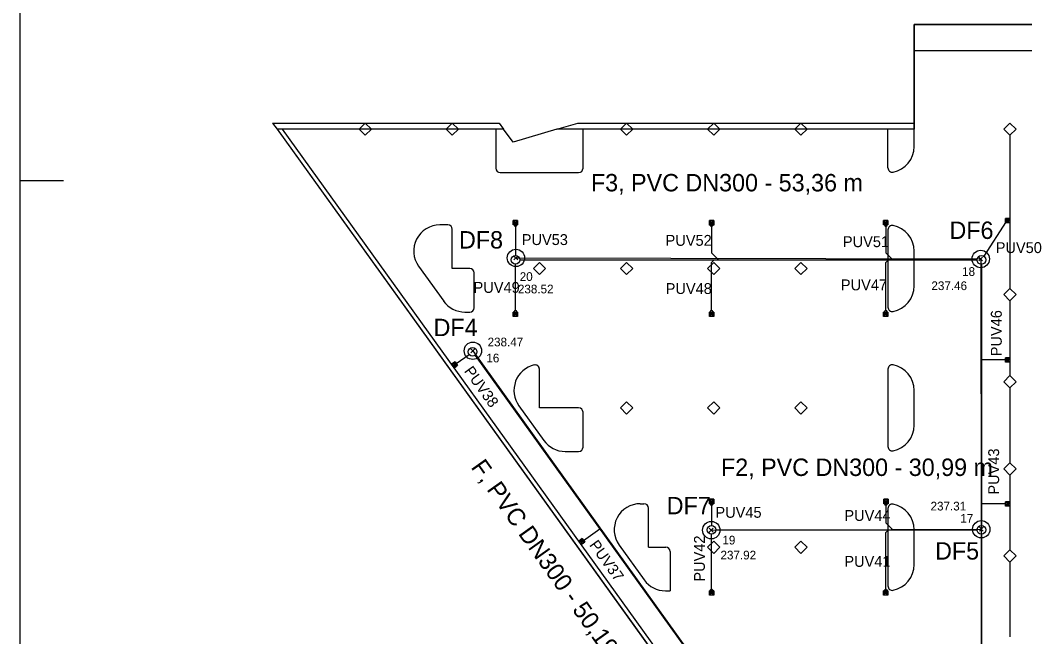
# Model space of a CAD drawing. Extents: x -264234 to -263604, y -1242346 to -1242049.
# Drawn here: x -264234.2 to -264118.9, y -1242249.8 to -1242179 of the extents above; entities that cross this region are included whole.
import ezdxf

# ---------------------------------------------------------------- set-up
doc = ezdxf.new("R2010")
doc.units = 0
for name, color, linetype in [('KFA_BODY_CISLO', 7, 'Continuous'), ('KFA_BODY_SYMBOL', 7, 'Continuous'), ('KFA_BODY_VYSKA', 7, 'Continuous'), ('KFA_DAZDOVA_KANALIZACIA_vetva_F', 7, 'Continuous'), ('KFA_DAZDOVA_KANALIZACIA_vetva_F_popis', 7, 'Continuous'), ('KFA_SITUACIA_DSP', 7, 'Continuous'), ('KFA_SO_40-2-II_DK_PRIPOJKY_UV_PROJEKT', 7, 'Continuous'), ('KFA_SO_40-2-II_DK_PRIPOJKY_UV_PROJEKT_popis', 7, 'Continuous'), ('KFA_SO_40-2-II_DK_UV_PROJEKT', 7, 'Continuous'), ('RAM_NA_TLAC_1-500', 7, 'Continuous')]:
    doc.layers.add(name, color=color, linetype=linetype)

msp = doc.modelspace()

# ---------------------------------------------------------------- linework, layer by layer
at = {"layer": 'KFA_BODY_SYMBOL'}
for p, q in [((-264177.49, -1242206.49), (-264177.05, -1242206.05)), ((-264177.05, -1242206.49), (-264177.49, -1242206.05)), ((-264124.14, -1242206.61), (-264123.7, -1242206.17)), ((-264123.7, -1242206.61), (-264124.14, -1242206.17)), ((-264182.44, -1242217.15), (-264181.99, -1242216.71)), ((-264181.99, -1242217.15), (-264182.44, -1242216.71)), ((-264155.08, -1242237.74), (-264154.63, -1242237.3)), ((-264154.63, -1242237.74), (-264155.08, -1242237.3)), ((-264124.08, -1242237.64), (-264123.64, -1242237.19)), ((-264123.64, -1242237.64), (-264124.08, -1242237.19))]:
    msp.add_line(p, q, dxfattribs=at)
at = {"layer": 'KFA_DAZDOVA_KANALIZACIA_vetva_F'}
msp.add_line((-264154.85, -1242237.52), (-264123.86, -1242237.42), dxfattribs=at)
for points in [[(-264177.27, -1242206.27), (-264123.92, -1242206.39), (-264123.86, -1242237.42), (-264123.84, -1242298.32)], [(-264182.21, -1242216.93), (-264152.95, -1242257.71), (-264123.84, -1242298.32)]]:
    msp.add_lwpolyline(points, dxfattribs=at)
for centre in [(-264177.27, -1242206.27), (-264123.92, -1242206.39), (-264182.21, -1242216.93), (-264154.85, -1242237.52), (-264123.86, -1242237.42)]:
    msp.add_circle(centre, 1, dxfattribs=at)
at = {"layer": 'KFA_SITUACIA_DSP'}
for p, q in [((-264131.57, -1242193.48), (-264131.57, -1242179.48)), ((-264077.23, -1242179.48), (-264131.57, -1242179.48)), ((-264131.57, -1242179.48), (-264131.57, -1242191.48)), ((-264131.57, -1242179.48), (-263959.47, -1242179.48)), ((-263959.47, -1242179.48), (-264131.57, -1242179.48)), ((-264045.2, -1242182.48), (-264131.57, -1242182.48)), ((-264205.2, -1242190.78), (-264179.19, -1242190.78)), ((-264205.2, -1242190.78), (-264204.69, -1242191.48)), ((-264178.68, -1242191.48), (-264204.69, -1242191.48)), ((-264204.69, -1242191.48), (-264115.87, -1242314.98)), ((-264179.57, -1242191.48), (-264204.08, -1242191.48)), ((-264204.08, -1242191.48), (-264119.75, -1242308.73)), ((-264179.57, -1242191.48), (-264179.57, -1242195.98)), ((-264179.19, -1242190.78), (-264178.68, -1242191.48)), ((-264177.6, -1242192.97), (-264178.68, -1242191.48)), ((-264172.56, -1242191.48), (-264177.6, -1242192.97)), ((-264172.56, -1242191.48), (-264170.16, -1242190.78)), ((-264131.57, -1242191.48), (-264172.56, -1242191.48)), ((-264170.16, -1242190.78), (-264131.57, -1242190.78)), ((-264134.57, -1242191.48), (-264169.57, -1242191.48)), ((-264169.57, -1242195.98), (-264169.57, -1242191.48)), ((-264134.57, -1242195.93), (-264134.57, -1242191.48)), ((-264120.57, -1242192.19), (-264120.57, -1242209.78)), ((-264179.07, -1242196.48), (-264170.07, -1242196.48)), ((-264121.01, -1242202.07), (-264123.58, -1242206.08)), ((-264120.86, -1242202.23), (-264120.86, -1242201.73)), ((-264120.86, -1242201.73), (-264120.57, -1242201.73)), ((-264120.86, -1242202.23), (-264120.57, -1242201.73)), ((-264120.86, -1242202.23), (-264120.57, -1242201.73)), ((-264120.57, -1242201.73), (-264120.86, -1242201.73)), ((-264120.86, -1242201.73), (-264120.86, -1242202.23)), ((-264120.57, -1242201.73), (-264120.57, -1242202.23)), ((-264185.07, -1242202.48), (-264186, -1242202.48)), ((-264177.57, -1242202.19), (-264177.07, -1242202.19)), ((-264177.57, -1242202.48), (-264177.57, -1242202.19)), ((-264177.57, -1242202.19), (-264177.07, -1242202.48)), ((-264177.57, -1242202.19), (-264177.07, -1242202.48)), ((-264177.07, -1242202.19), (-264177.57, -1242202.19)), ((-264177.07, -1242202.48), (-264177.57, -1242202.48)), ((-264177.32, -1242202.68), (-264177.32, -1242205.98)), ((-264177.07, -1242202.19), (-264177.07, -1242202.48)), ((-264177.07, -1242202.48), (-264177.07, -1242202.19)), ((-264155.07, -1242202.19), (-264154.57, -1242202.19)), ((-264155.07, -1242202.48), (-264155.07, -1242202.19)), ((-264155.07, -1242202.19), (-264154.57, -1242202.48)), ((-264155.07, -1242202.19), (-264154.57, -1242202.48)), ((-264154.57, -1242202.19), (-264155.07, -1242202.19)), ((-264154.57, -1242202.48), (-264155.07, -1242202.48)), ((-264154.82, -1242202.68), (-264154.82, -1242205.68)), ((-264154.57, -1242202.19), (-264154.57, -1242202.48)), ((-264154.57, -1242202.48), (-264154.57, -1242202.19)), ((-264135.07, -1242202.19), (-264134.57, -1242202.19)), ((-264135.07, -1242202.48), (-264135.07, -1242202.19)), ((-264135.07, -1242202.19), (-264134.57, -1242202.48)), ((-264135.07, -1242202.19), (-264134.57, -1242202.48)), ((-264134.57, -1242202.19), (-264135.07, -1242202.19)), ((-264134.57, -1242202.48), (-264135.07, -1242202.48)), ((-264134.82, -1242202.68), (-264134.82, -1242205.68)), ((-264134.57, -1242202.19), (-264134.57, -1242202.48)), ((-264134.57, -1242202.48), (-264134.57, -1242202.19)), ((-264134.57, -1242203.03), (-264134.57, -1242211.93)), ((-264120.57, -1242202.23), (-264120.86, -1242202.23)), ((-264131.57, -1242209.48), (-264131.57, -1242205.48)), ((-264176.82, -1242206.48), (-264124.35, -1242206.48)), ((-264154.82, -1242205.68), (-264154.03, -1242206.48)), ((-264154.82, -1242206.8), (-264154.5, -1242206.48)), ((-264134.82, -1242205.68), (-264134.02, -1242206.48)), ((-264134.82, -1242206.8), (-264134.49, -1242206.48)), ((-264188.44, -1242207.23), (-264185.56, -1242211.23)), ((-264177.32, -1242212.28), (-264177.32, -1242206.98)), ((-264154.82, -1242212.28), (-264154.82, -1242206.8)), ((-264134.82, -1242212.28), (-264134.82, -1242206.8)), ((-264123.85, -1242207), (-264123.85, -1242236.98)), ((-264182.07, -1242211.98), (-264182.07, -1242207.98)), ((-264120.57, -1242211.19), (-264120.57, -1242219.77)), ((-264183.13, -1242212.48), (-264182.57, -1242212.48)), ((-264177.57, -1242212.48), (-264177.07, -1242212.48)), ((-264177.57, -1242212.77), (-264177.57, -1242212.48)), ((-264177.57, -1242212.48), (-264177.07, -1242212.77)), ((-264177.57, -1242212.48), (-264177.07, -1242212.77)), ((-264177.07, -1242212.48), (-264177.57, -1242212.48)), ((-264177.07, -1242212.48), (-264177.07, -1242212.77)), ((-264177.07, -1242212.77), (-264177.07, -1242212.48)), ((-264155.07, -1242212.48), (-264154.57, -1242212.48)), ((-264155.07, -1242212.77), (-264155.07, -1242212.48)), ((-264155.07, -1242212.48), (-264154.57, -1242212.77)), ((-264155.07, -1242212.48), (-264154.57, -1242212.77)), ((-264154.57, -1242212.48), (-264155.07, -1242212.48)), ((-264154.57, -1242212.48), (-264154.57, -1242212.77)), ((-264154.57, -1242212.77), (-264154.57, -1242212.48)), ((-264135.07, -1242212.48), (-264134.57, -1242212.48)), ((-264135.07, -1242212.77), (-264135.07, -1242212.48)), ((-264135.07, -1242212.48), (-264134.57, -1242212.77)), ((-264135.07, -1242212.48), (-264134.57, -1242212.77)), ((-264134.57, -1242212.48), (-264135.07, -1242212.48)), ((-264134.57, -1242212.48), (-264134.57, -1242212.77)), ((-264134.57, -1242212.77), (-264134.57, -1242212.48)), ((-264177.07, -1242212.77), (-264177.57, -1242212.77)), ((-264154.57, -1242212.77), (-264155.07, -1242212.77)), ((-264134.57, -1242212.77), (-264135.07, -1242212.77)), ((-264184.12, -1242218.4), (-264182.65, -1242217.34)), ((-264181.95, -1242217.46), (-264153.34, -1242257.24)), ((-264121.06, -1242217.98), (-264123.85, -1242217.98)), ((-264120.86, -1242218.23), (-264120.86, -1242217.73)), ((-264120.86, -1242217.73), (-264120.57, -1242217.73)), ((-264120.86, -1242218.23), (-264120.57, -1242217.73)), ((-264120.86, -1242218.23), (-264120.57, -1242217.73)), ((-264120.57, -1242217.73), (-264120.86, -1242217.73)), ((-264120.86, -1242217.73), (-264120.86, -1242218.23)), ((-264120.57, -1242218.23), (-264120.86, -1242218.23)), ((-264120.57, -1242217.73), (-264120.57, -1242218.23)), ((-264184.66, -1242218.48), (-264184.42, -1242218.31)), ((-264184.37, -1242218.89), (-264184.66, -1242218.48)), ((-264184.42, -1242218.31), (-264184.13, -1242218.72)), ((-264184.42, -1242218.31), (-264184.37, -1242218.89)), ((-264184.42, -1242218.31), (-264184.37, -1242218.89)), ((-264184.13, -1242218.72), (-264184.42, -1242218.31)), ((-264184.13, -1242218.72), (-264184.37, -1242218.89)), ((-264184.37, -1242218.89), (-264184.13, -1242218.72)), ((-264134.57, -1242219.03), (-264134.57, -1242227.93)), ((-264131.57, -1242225.48), (-264131.57, -1242221.48)), ((-264120.57, -1242221.19), (-264120.57, -1242229.77)), ((-264176.93, -1242223.23), (-264174.05, -1242227.23)), ((-264169.57, -1242227.98), (-264169.57, -1242223.98)), ((-264171.62, -1242228.48), (-264170.07, -1242228.48)), ((-264120.57, -1242231.19), (-264120.57, -1242239.77)), ((-264155.07, -1242234.19), (-264154.57, -1242234.19)), ((-264155.07, -1242234.48), (-264155.07, -1242234.19)), ((-264155.07, -1242234.19), (-264154.57, -1242234.48)), ((-264155.07, -1242234.19), (-264154.57, -1242234.48)), ((-264154.57, -1242234.19), (-264155.07, -1242234.19)), ((-264154.57, -1242234.19), (-264154.57, -1242234.48)), ((-264154.57, -1242234.48), (-264154.57, -1242234.19)), ((-264135.06, -1242234.19), (-264134.56, -1242234.19)), ((-264135.06, -1242234.48), (-264135.06, -1242234.19)), ((-264135.06, -1242234.19), (-264134.56, -1242234.48)), ((-264135.06, -1242234.19), (-264134.56, -1242234.48)), ((-264134.56, -1242234.19), (-264135.06, -1242234.19)), ((-264134.56, -1242234.19), (-264134.56, -1242234.48)), ((-264134.56, -1242234.48), (-264134.56, -1242234.19)), ((-264120.86, -1242234.75), (-264120.86, -1242234.25)), ((-264120.86, -1242234.25), (-264120.57, -1242234.25)), ((-264120.86, -1242234.75), (-264120.57, -1242234.25)), ((-264120.86, -1242234.75), (-264120.57, -1242234.25)), ((-264120.57, -1242234.25), (-264120.86, -1242234.25)), ((-264120.86, -1242234.25), (-264120.86, -1242234.75)), ((-264120.57, -1242234.25), (-264120.57, -1242234.75)), ((-264162.99, -1242234.48), (-264162.57, -1242234.48)), ((-264162.07, -1242239.48), (-264162.07, -1242234.98)), ((-264154.57, -1242234.48), (-264155.07, -1242234.48)), ((-264154.82, -1242234.68), (-264154.82, -1242236.98)), ((-264134.56, -1242234.48), (-264135.06, -1242234.48)), ((-264134.81, -1242234.68), (-264134.81, -1242236.68)), ((-264134.57, -1242235.03), (-264134.57, -1242243.93)), ((-264121.06, -1242234.5), (-264123.85, -1242234.5)), ((-264120.57, -1242234.75), (-264120.86, -1242234.75)), ((-264134.81, -1242236.68), (-264134.02, -1242237.48)), ((-264169.52, -1242238.7), (-264167.65, -1242237.35)), ((-264154.32, -1242237.48), (-264124.35, -1242237.48)), ((-264134.81, -1242237.8), (-264134.49, -1242237.48)), ((-264134.81, -1242244.28), (-264134.81, -1242237.8)), ((-264131.57, -1242241.48), (-264131.57, -1242237.48)), ((-264170.06, -1242238.78), (-264169.83, -1242238.61)), ((-264169.77, -1242239.18), (-264170.06, -1242238.78)), ((-264169.83, -1242238.61), (-264169.53, -1242239.01)), ((-264169.83, -1242238.61), (-264169.77, -1242239.18)), ((-264169.83, -1242238.61), (-264169.77, -1242239.18)), ((-264169.53, -1242239.01), (-264169.83, -1242238.61)), ((-264169.53, -1242239.01), (-264169.77, -1242239.18)), ((-264169.77, -1242239.18), (-264169.53, -1242239.01)), ((-264154.82, -1242244.28), (-264154.82, -1242237.98)), ((-264123.85, -1242237.98), (-264123.85, -1242297.74)), ((-264165.42, -1242239.23), (-264162.55, -1242243.23)), ((-264162.07, -1242239.48), (-264160.07, -1242239.48)), ((-264159.57, -1242239.98), (-264159.57, -1242244.48)), ((-264120.57, -1242241.19), (-264120.57, -1242249.77)), ((-264160.11, -1242244.48), (-264159.57, -1242244.48)), ((-264155.07, -1242244.48), (-264154.57, -1242244.48)), ((-264155.07, -1242244.77), (-264155.07, -1242244.48)), ((-264155.07, -1242244.48), (-264154.57, -1242244.77)), ((-264155.07, -1242244.48), (-264154.57, -1242244.77)), ((-264154.57, -1242244.48), (-264155.07, -1242244.48)), ((-264154.57, -1242244.77), (-264155.07, -1242244.77)), ((-264154.57, -1242244.48), (-264154.57, -1242244.77)), ((-264154.57, -1242244.77), (-264154.57, -1242244.48)), ((-264135.07, -1242244.48), (-264134.57, -1242244.48)), ((-264135.07, -1242244.77), (-264135.07, -1242244.48)), ((-264135.07, -1242244.48), (-264134.57, -1242244.77)), ((-264135.07, -1242244.48), (-264134.57, -1242244.77)), ((-264134.57, -1242244.48), (-264135.07, -1242244.48)), ((-264134.57, -1242244.77), (-264135.07, -1242244.77)), ((-264134.57, -1242244.48), (-264134.57, -1242244.77)), ((-264134.57, -1242244.77), (-264134.57, -1242244.48))]:
    msp.add_line(p, q, dxfattribs=at)
for points in [[(-264204.69, -1242191.48), (-264137.78, -1242284.52), (-264125.58, -1242301.48)], [(-264193.86, -1242191.48), (-264193.86, -1242191.48), (-264194.57, -1242192.19), (-264195.27, -1242191.48)], [(-264183.86, -1242191.48), (-264183.86, -1242191.48), (-264184.57, -1242192.19), (-264185.27, -1242191.48)], [(-264163.86, -1242191.48), (-264163.86, -1242191.48), (-264164.57, -1242192.19), (-264165.27, -1242191.48)], [(-264153.86, -1242191.48), (-264153.86, -1242191.48), (-264154.57, -1242192.19), (-264155.27, -1242191.48)], [(-264143.86, -1242191.48), (-264143.86, -1242191.48), (-264144.57, -1242192.19), (-264145.27, -1242191.48)], [(-264182.57, -1242207.48), (-264184.57, -1242207.48), (-264184.57, -1242202.98)], [(-264170.07, -1242223.48), (-264174.57, -1242223.48), (-264174.57, -1242219.05)]]:
    msp.add_lwpolyline(points, dxfattribs=at)
for points in [[(-264194.57, -1242190.78), (-264193.86, -1242191.48), (-264194.57, -1242192.19), (-264195.27, -1242191.48)], [(-264184.57, -1242190.78), (-264183.86, -1242191.48), (-264184.57, -1242192.19), (-264185.27, -1242191.48)], [(-264164.57, -1242190.78), (-264163.86, -1242191.48), (-264164.57, -1242192.19), (-264165.27, -1242191.48)], [(-264154.57, -1242190.78), (-264153.86, -1242191.48), (-264154.57, -1242192.19), (-264155.27, -1242191.48)], [(-264144.57, -1242190.78), (-264143.86, -1242191.48), (-264144.57, -1242192.19), (-264145.27, -1242191.48)], [(-264120.57, -1242190.78), (-264119.86, -1242191.48), (-264120.57, -1242192.19), (-264121.27, -1242191.48)], [(-264173.86, -1242207.48), (-264174.57, -1242206.78), (-264175.27, -1242207.48), (-264174.57, -1242208.19)], [(-264163.86, -1242207.48), (-264164.57, -1242206.78), (-264165.27, -1242207.48), (-264164.57, -1242208.19)], [(-264153.86, -1242207.48), (-264154.57, -1242206.78), (-264155.27, -1242207.48), (-264154.57, -1242208.19)], [(-264143.86, -1242207.48), (-264144.57, -1242206.78), (-264145.27, -1242207.48), (-264144.57, -1242208.19)], [(-264120.57, -1242209.78), (-264119.86, -1242210.48), (-264120.57, -1242211.19), (-264121.27, -1242210.48)], [(-264120.57, -1242219.78), (-264119.86, -1242220.48), (-264120.57, -1242221.19), (-264121.27, -1242220.48)], [(-264163.86, -1242223.48), (-264164.57, -1242222.78), (-264165.27, -1242223.48), (-264164.57, -1242224.19)], [(-264153.86, -1242223.48), (-264154.57, -1242222.78), (-264155.27, -1242223.48), (-264154.57, -1242224.19)], [(-264143.86, -1242223.48), (-264144.57, -1242222.78), (-264145.27, -1242223.48), (-264144.57, -1242224.19)], [(-264120.57, -1242229.78), (-264119.86, -1242230.48), (-264120.57, -1242231.19), (-264121.27, -1242230.48)], [(-264153.86, -1242239.48), (-264154.57, -1242238.78), (-264155.27, -1242239.48), (-264154.57, -1242240.19)], [(-264143.86, -1242239.48), (-264144.57, -1242238.78), (-264145.27, -1242239.48), (-264144.57, -1242240.19)], [(-264120.57, -1242239.78), (-264119.86, -1242240.48), (-264120.57, -1242241.19), (-264121.27, -1242240.48)]]:
    msp.add_lwpolyline(points, close=True, dxfattribs=at)
for centre, radius in [((-264120.96, -1242201.98), 0.1), ((-264177.32, -1242202.58), 0.1), ((-264154.82, -1242202.58), 0.1), ((-264134.82, -1242202.58), 0.1), ((-264177.32, -1242206.48), 0.5), ((-264123.85, -1242206.5), 0.5), ((-264177.32, -1242212.38), 0.1), ((-264154.82, -1242212.38), 0.1), ((-264134.82, -1242212.38), 0.1), ((-264182.24, -1242217.05), 0.5), ((-264120.96, -1242217.98), 0.1), ((-264184.19, -1242218.46), 0.1), ((-264120.96, -1242234.5), 0.1), ((-264154.82, -1242234.58), 0.1), ((-264134.81, -1242234.58), 0.1), ((-264154.82, -1242237.48), 0.5), ((-264123.85, -1242237.48), 0.5), ((-264169.6, -1242238.76), 0.1), ((-264154.82, -1242244.38), 0.1), ((-264134.81, -1242244.38), 0.1)]:
    msp.add_circle(centre, radius, dxfattribs=at)
for centre, radius, start, end in [((-264134.57, -1242193.48), 3, 281.537, 0), ((-264179.07, -1242195.98), 0.5, 180, 270), ((-264170.07, -1242195.98), 0.5, 270, 0), ((-264134.07, -1242195.93), 0.5, 180, 281.537), ((-264186, -1242205.48), 3, 90, 215.724), ((-264185.07, -1242202.98), 0.5, 0, 90), ((-264134.07, -1242203.03), 0.5, 78.463, 180), ((-264134.57, -1242205.48), 3, 0, 78.463), ((-264182.57, -1242207.98), 0.5, 0, 90), ((-264134.57, -1242209.48), 3, 281.537, 0), ((-264183.13, -1242209.48), 3, 215.724, 270), ((-264182.57, -1242211.98), 0.5, 270, 0), ((-264134.07, -1242211.93), 0.5, 180, 281.537), ((-264174.49, -1242221.48), 3, 103.2476, 215.724), ((-264175.07, -1242219.05), 0.5, 0, 103.2476), ((-264134.07, -1242219.03), 0.5, 78.463, 180), ((-264134.57, -1242221.48), 3, 0, 78.463), ((-264170.07, -1242223.98), 0.5, 0, 90), ((-264134.57, -1242225.48), 3, 281.537, 0), ((-264171.62, -1242225.48), 3, 215.724, 270), ((-264170.07, -1242227.98), 0.5, 270, 0), ((-264134.07, -1242227.93), 0.5, 180, 281.537), ((-264162.99, -1242237.48), 3, 90, 215.724), ((-264162.57, -1242234.98), 0.5, 0, 90), ((-264134.07, -1242235.03), 0.5, 78.463, 180), ((-264134.57, -1242237.48), 3, 0, 78.463), ((-264160.07, -1242239.98), 0.5, 0, 90), ((-264134.57, -1242241.48), 3, 281.537, 0), ((-264160.11, -1242241.48), 3, 215.724, 270), ((-264134.07, -1242243.93), 0.5, 180, 281.537)]:
    msp.add_arc(centre, radius, start, end, dxfattribs=at)
at = {"layer": 'KFA_SO_40-2-II_DK_PRIPOJKY_UV_PROJEKT'}
for points in [[(-264121.01, -1242202.07), (-264123.58, -1242206.08)], [(-264177.32, -1242202.68), (-264177.32, -1242205.98)], [(-264154.82, -1242202.68), (-264154.82, -1242205.68), (-264154.03, -1242206.48)], [(-264134.82, -1242202.68), (-264134.82, -1242205.68), (-264134.02, -1242206.48)], [(-264154.82, -1242212.28), (-264154.82, -1242206.8), (-264154.5, -1242206.48)], [(-264134.82, -1242212.28), (-264134.82, -1242206.8), (-264134.49, -1242206.48)], [(-264177.32, -1242212.28), (-264177.32, -1242206.98)], [(-264184.12, -1242218.4), (-264182.65, -1242217.34)], [(-264121.06, -1242217.98), (-264123.85, -1242217.98)], [(-264154.82, -1242234.68), (-264154.82, -1242236.98)], [(-264134.81, -1242234.68), (-264134.81, -1242236.68), (-264134.02, -1242237.48)], [(-264121.06, -1242234.5), (-264123.85, -1242234.5)], [(-264169.52, -1242238.7), (-264167.65, -1242237.35)], [(-264134.81, -1242244.28), (-264134.81, -1242237.8), (-264134.49, -1242237.48)], [(-264154.82, -1242244.28), (-264154.82, -1242237.98)]]:
    msp.add_lwpolyline(points, dxfattribs=at)
msp.add_circle((-264120.96, -1242201.98), 0.1, dxfattribs=at)
at = {"layer": 'KFA_SO_40-2-II_DK_UV_PROJEKT'}
for points in [[(-264177.57, -1242202.48), (-264177.57, -1242201.98), (-264177.07, -1242201.98), (-264177.07, -1242202.48), (-264177.57, -1242202.48), (-264177.07, -1242201.98), (-264177.57, -1242201.98), (-264177.07, -1242202.48)], [(-264155.07, -1242202.49), (-264155.07, -1242201.99), (-264154.57, -1242201.99), (-264154.57, -1242202.49), (-264155.07, -1242202.49), (-264154.57, -1242201.99), (-264155.07, -1242201.99), (-264154.57, -1242202.49)], [(-264135.07, -1242202.48), (-264135.07, -1242201.98), (-264134.57, -1242201.98), (-264134.57, -1242202.48), (-264135.07, -1242202.48), (-264134.57, -1242201.98), (-264135.07, -1242201.98), (-264134.57, -1242202.48)], [(-264121.07, -1242202.23), (-264121.07, -1242201.73), (-264120.57, -1242201.73), (-264120.57, -1242202.23), (-264121.07, -1242202.23), (-264120.57, -1242201.73), (-264121.07, -1242201.73), (-264120.57, -1242202.23)], [(-264177.57, -1242212.98), (-264177.57, -1242212.48), (-264177.07, -1242212.48), (-264177.07, -1242212.98), (-264177.57, -1242212.98), (-264177.07, -1242212.48), (-264177.57, -1242212.48), (-264177.07, -1242212.98)], [(-264155.07, -1242212.98), (-264155.07, -1242212.48), (-264154.57, -1242212.48), (-264154.57, -1242212.98), (-264155.07, -1242212.98), (-264154.57, -1242212.48), (-264155.07, -1242212.48), (-264154.57, -1242212.98)], [(-264135.07, -1242212.98), (-264135.07, -1242212.48), (-264134.57, -1242212.48), (-264134.57, -1242212.98), (-264135.07, -1242212.98), (-264134.57, -1242212.48), (-264135.07, -1242212.48), (-264134.57, -1242212.98)], [(-264184.37, -1242218.89), (-264184.66, -1242218.48), (-264184.25, -1242218.19), (-264183.96, -1242218.6), (-264184.37, -1242218.89), (-264184.25, -1242218.19), (-264184.66, -1242218.48), (-264183.96, -1242218.6)], [(-264121.07, -1242218.23), (-264121.07, -1242217.73), (-264120.57, -1242217.73), (-264120.57, -1242218.23), (-264121.07, -1242218.23), (-264120.57, -1242217.73), (-264121.07, -1242217.73), (-264120.57, -1242218.23)], [(-264155.07, -1242234.48), (-264155.07, -1242233.98), (-264154.57, -1242233.98), (-264154.57, -1242234.48), (-264155.07, -1242234.48), (-264154.57, -1242233.98), (-264155.07, -1242233.98), (-264154.57, -1242234.48)], [(-264135.06, -1242234.48), (-264135.06, -1242233.98), (-264134.56, -1242233.98), (-264134.56, -1242234.48), (-264135.06, -1242234.48), (-264134.56, -1242233.98), (-264135.06, -1242233.98), (-264134.56, -1242234.48)], [(-264121.07, -1242234.75), (-264121.07, -1242234.25), (-264120.57, -1242234.25), (-264120.57, -1242234.75), (-264121.07, -1242234.75), (-264120.57, -1242234.25), (-264121.07, -1242234.25), (-264120.57, -1242234.75)], [(-264169.77, -1242239.18), (-264170.06, -1242238.78), (-264169.66, -1242238.49), (-264169.36, -1242238.89), (-264169.77, -1242239.18), (-264169.66, -1242238.49), (-264170.06, -1242238.78), (-264169.36, -1242238.89)], [(-264155.07, -1242244.98), (-264155.07, -1242244.48), (-264154.57, -1242244.48), (-264154.57, -1242244.98), (-264155.07, -1242244.98), (-264154.57, -1242244.48), (-264155.07, -1242244.48), (-264154.57, -1242244.98)], [(-264135.07, -1242244.98), (-264135.07, -1242244.48), (-264134.57, -1242244.48), (-264134.57, -1242244.98), (-264135.07, -1242244.98), (-264134.57, -1242244.48), (-264135.07, -1242244.48), (-264134.57, -1242244.98)]]:
    msp.add_lwpolyline(points, dxfattribs=at)
at = {"layer": 'RAM_NA_TLAC_1-500'}
msp.add_line((-264234.18, -1242197.38), (-264229.18, -1242197.38), dxfattribs=at)
msp.add_lwpolyline([(-264234.18, -1242048.88), (-263604.18, -1242048.88), (-263604.18, -1242345.88), (-264234.18, -1242345.88)], close=True, dxfattribs=at)

# ---------------------------------------------------------------- texts
at = {"layer": 'KFA_BODY_CISLO'}
for s, p in [('18', (-264126.06, -1242208.33)), ('20', (-264176.83, -1242208.91)), ('16', (-264180.66, -1242218.26)), ('17', (-264126.27, -1242236.67)), ('19', (-264153.57, -1242239.16))]:
    msp.add_text(s, height=1, dxfattribs=at).set_placement(p)
at = {"layer": 'KFA_BODY_VYSKA'}
for s, p in [('237.46', (-264129.58, -1242209.96)), ('238.52', (-264177.04, -1242210.34)), ('238.47', (-264180.52, -1242216.42)), ('237.31', (-264129.68, -1242235.26)), ('237.92', (-264153.79, -1242240.88))]:
    msp.add_text(s, height=1, dxfattribs=at).set_placement(p)
at = {"layer": 'KFA_DAZDOVA_KANALIZACIA_vetva_F_popis'}
for s, p in [('F3, PVC DN300 - 53,36 m', (-264168.66, -1242198.63)), ('DF6', (-264127.51, -1242204.09)), ('DF8', (-264183.8, -1242205.19)), ('DF4', (-264186.72, -1242215.25)), ('F2, PVC DN300 - 30,99 m', (-264153.73, -1242231.3)), ('DF7', (-264159.96, -1242235.7)), ('DF5', (-264129.16, -1242240.9))]:
    msp.add_text(s, height=2, dxfattribs=at).set_placement(p)
msp.add_text('F, PVC DN300 - 50,19 m', height=2, rotation=305.4236, dxfattribs=at).set_placement((-264182.5, -1242230.3))
at = {"layer": 'KFA_SO_40-2-II_DK_PRIPOJKY_UV_PROJEKT_popis'}
for s, p in [('PUV53', (-264176.6, -1242204.79)), ('PUV52', (-264160.09, -1242204.88)), ('PUV51', (-264139.74, -1242205.03)), ('PUV50', (-264122.2, -1242205.71)), ('PUV49', (-264182.13, -1242210.28)), ('PUV47', (-264139.97, -1242209.99)), ('PUV48', (-264160.08, -1242210.41)), ('PUV45', (-264154.37, -1242236.1)), ('PUV44', (-264139.57, -1242236.46)), ('PUV41', (-264139.57, -1242241.73))]:
    msp.add_text(s, height=1.25, dxfattribs=at).set_placement(p)
for s, rotation, p in [('PUV46', 90, (-264121.51, -1242217.56)), ('PUV38', 305.724, (-264183.27, -1242219.26)), ('PUV43', 90, (-264121.81, -1242233.44)), ('PUV37', 305.724, (-264168.9, -1242239.23)), ('PUV42', 90, (-264155.58, -1242243.43))]:
    msp.add_text(s, height=1.25, rotation=rotation, dxfattribs=at).set_placement(p)

doc.saveas('drawing.dxf')
